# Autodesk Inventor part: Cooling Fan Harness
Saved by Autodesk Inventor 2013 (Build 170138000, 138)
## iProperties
GlobalPropertyList: <PropertyList/>
Key:2|1|1|0|8|0|0|0|1|0|0|0|28|0|0|0|Level:2: <CableProperty entityType="Connector" version="1.0"><ID editable="" value=""/><UserDefined><Property name="14121" value="0 mm" unitCategory="14110" custom="Fals
Key:2|1|1|0|4|0|0|0|18|0|0|0|Level:1: <CableProperty entityType="Connector" version="1.0"><ID editable="" value=""/><UserDefined><Property name="14121" value="0.125 in" unitCategory="14110" custom="
Created: 2007-02
Part Number: Cooling Fan Harness
Document SubType Name: Modeling
Designer: floress
Density: 1 g/cm^3
Material: Allgemein
Author: floress
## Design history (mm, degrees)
workpoint "Work Point1"
workpoint "Work Point2"
sketch "Segment1"
workpoint "Work Point3"
workpoint "Work Point4"
workpoint "Work Point5"
workpoint "Work Point6"
workpoint "Work Point7"
workpoint "Work Point8"
workpoint "Work Point9"
workpoint "Work Point10"
workpoint "Work Point11"
workpoint "Work Point12"
sketch "Wire1"
workpoint "Work Point13"
workpoint "Work Point14"
sketch "Wire2"
workplane "Work Plane1"
sketch "Sketch1"
  geometry: C1 r 0.762 at (0, 0); 1 further point
  constraints: 1 centre point
feature "SweepSrf1" sketch "Sketch1" dims "d0" = 0
workplane "Work Plane2"
sketch "Sketch2"
  geometry: C1 r 0.381 at (0, 0); 1 further point
  constraints: 1 centre point
feature "SweepSrf2" sketch "Sketch2" dims "d1" = 0
workplane "Work Plane3"
sketch "Sketch3"
  geometry: C1 r 0.381 at (0, 0); 1 further point
  constraints: 1 centre point
feature "SweepSrf3" sketch "Sketch3" dims "d2" = 0
workplane "Work Plane4"
sketch "Sketch4"
  geometry: C1 r 0.381 at (0, 0); 1 further point
  constraints: 1 centre point
feature "SweepSrf4" sketch "Sketch4" dims "d3" = 0
workplane "Work Plane5"
sketch "Sketch5"
  geometry: C1 r 0.381 at (0, 0); 1 further point
  constraints: 1 centre point
feature "SweepSrf5" sketch "Sketch5" dims "d4" = 0
body "Srf1"
body "Srf2"
body "Srf3"
body "Srf4"
body "Srf5"
